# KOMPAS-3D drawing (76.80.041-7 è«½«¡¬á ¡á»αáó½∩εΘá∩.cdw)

Views: Вид 1
Referenced files in C:\Users\ptitsin\Desktop\Базовая грузовые\: ПТФ 436200.20.42 Колонка направляющая.cdw
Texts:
  Цементировать h 1...1,5 мм; 54...58 HRC.
  h14,  IT 14/2.
  Ra 6,3
  Ra 6,3 ( )
  GOST2.303 5_RGB_255_0_0_SC_1_THICK_0.25
  ПТФ 436200.20.42
  Колонка
  направляющая
  Сталь 20 ГОСТ 1050-88
  ООО "ЗАВОД МАРКОН"
  ПТФ 436200.20.42-
  Птицин
  Т. директор
  Хомутов
  Мардаков
  Колонка направляющая
Dimensions and other numbers on the sheet: 276; 60; 330; 1,5х45; 120; 2,5; 1,6; 0,8; 36; 0,02; 1; 0,5; 1,5; 12; 46; 50; 49; 4; 1:1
